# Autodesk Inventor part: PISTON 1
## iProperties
Created: 2004-11
Part Number: PISTON 1
Document SubType Name: Modeling
Designer: Bruno
Manufacturer: Standard
Standards Organization: Custom
Author: Bruno
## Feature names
1. Base1
